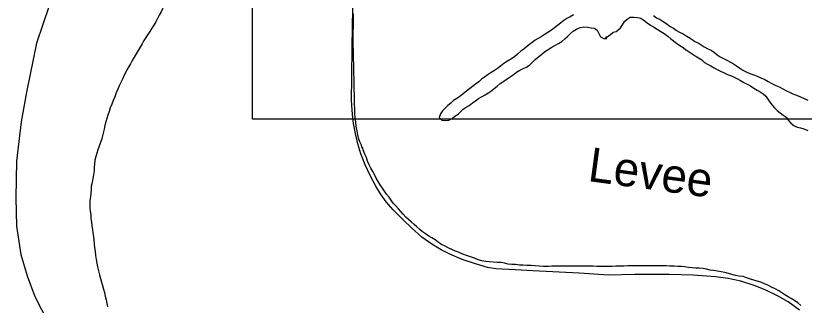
# Model space of a CAD drawing. Extents: x 1945482 to 2853149, y 66427 to 1015778.
# Drawn here: x 2297099 to 2300512, y 198481 to 199733 of the extents above; entities that cross this region are included whole.
import ezdxf

# ---------------------------------------------------------------- set-up
doc = ezdxf.new("R2010")
doc.units = 0
for name, color, linetype in [('Old_Level_21', 7, 'Continuous'), ('Old_Level_3', 7, 'Continuous'), ('Old_Level_35', 7, 'Continuous'), ('Old_Level_52', 7, 'Continuous'), ('Old_Level_60', 7, 'Continuous')]:
    doc.layers.add(name, color=color, linetype=linetype)

msp = doc.modelspace()

# ---------------------------------------------------------------- linework, layer by layer
at = {"layer": 'Old_Level_3'}
msp.add_lwpolyline([(2304961.1, 199286.1), (2298124.6, 199286.1), (2298124.6, 202204.8), (2304961.1, 202204.8), (2304961.1, 199286.1)], dxfattribs=at)
at = {"layer": 'Old_Level_35'}
msp.add_lwpolyline([(2300491.7, 198459.2), (2300442.2, 198495), (2300395.9, 198521.4), (2300342.9, 198547.7), (2300295.4, 198566.4), (2300237.4, 198584.2), (2300183.1, 198595.8), (2300127.2, 198603.1), (2300030.9, 198610.2), (2299927, 198613.5), (2299779.1, 198614.1), (2299665.2, 198611.1), (2299537.2, 198620.1), (2299337, 198630.3), (2299260.9, 198633.7), (2299177.1, 198638.9), (2299140.8, 198644.6), (2299088.9, 198660.3), (2299030.6, 198678.9), (2298978.6, 198701.2), (2298940.2, 198721), (2298900, 198744.4), (2298856.4, 198775.7), (2298811.5, 198815.6), (2298777.1, 198849.4), (2298733, 198892.9), (2298702.9, 198928.3), (2298678.3, 198962.5), (2298658, 198996.4), (2298633.6, 199042.1), (2298611.8, 199087.8), (2298592.8, 199135.7), (2298580.2, 199179.6), (2298569.9, 199223.4), (2298561.6, 199267.5), (2298557, 199305.3), (2298552.7, 199367.4), (2298553.9, 199465.4), (2298554.6, 199599.2), (2298557.5, 199765.5)], dxfattribs=at)
at = {"layer": 'Old_Level_52'}
msp.add_lwpolyline([(2297903, 202210.8), (2297795.6, 201641.6), (2297622.1, 200907.6), (2297545.5, 200618.8), (2297392.5, 200193.1), (2297315, 199980.3), (2297243.4, 199775.5), (2297189.3, 199614.8), (2297146.2, 199401.9), (2297123.3, 199274), (2297103.2, 199103.9), (2297099.5, 198945.2), (2297102.1, 198822.2), (2297121.9, 198700.2), (2297149.1, 198608.5), (2297182.1, 198518.9), (2297241.5, 198403.6)], dxfattribs=at)
at = {"layer": 'Old_Level_60'}
for points in [[(2297754.5, 199805.8), (2297747.7, 199791.4), (2297741.5, 199777.4), (2297735, 199763.4), (2297728.2, 199749.6), (2297720.7, 199735.4), (2297713.2, 199721.2)], [(2297713.2, 199721.2), (2297705.5, 199706.8), (2297697.2, 199692.8), (2297688.5, 199679.2), (2297679.5, 199665.2), (2297670.5, 199651.8), (2297662.2, 199638.6), (2297653.7, 199625.4), (2297646, 199611.6), (2297638, 199597.2), (2297629.5, 199582.6), (2297621, 199568.4), (2297612.2, 199553.8), (2297603.7, 199539.2), (2297595.5, 199525), (2297587.5, 199511.4), (2297580.5, 199498), (2297570.7, 199479.4), (2297560.7, 199458.6), (2297554.2, 199444.8), (2297547.5, 199430.4), (2297540.7, 199415.2), (2297534, 199399.4), (2297527.5, 199382.8), (2297521, 199366.2), (2297514.5, 199350.2), (2297508.7, 199334.2), (2297503.2, 199318.8), (2297498.2, 199303.6), (2297493.5, 199288.4), (2297489.2, 199273.6), (2297485.2, 199258), (2297481.5, 199241.8), (2297477.5, 199224.8), (2297473.5, 199208.2), (2297471.5, 199200), (2297454.7, 199153.4), (2297450.2, 199139.2), (2297445.5, 199123.6), (2297441.7, 199108.4), (2297440.5, 199093.2), (2297438.5, 199077), (2297438.2, 199061.6), (2297435.5, 199045.4), (2297432.5, 199029), (2297430, 199012.2), (2297426, 198996.2), (2297425.5, 198980.8), (2297425, 198965.2), (2297422.5, 198949.6), (2297420.5, 198934), (2297420.5, 198917.8), (2297420.5, 198902.6), (2297421.2, 198887.4), (2297424.5, 198871.4), (2297424.5, 198856.2), (2297427.7, 198840.8), (2297429.2, 198824.2), (2297431.2, 198808.4), (2297433.5, 198793.4), (2297435.7, 198778.2), (2297437.7, 198761.8), (2297438.5, 198745), (2297440.5, 198730), (2297442.5, 198714.6), (2297444.5, 198696), (2297447.2, 198679), (2297450.2, 198662.4), (2297453.7, 198646.8), (2297457.7, 198629), (2297462.5, 198612.2), (2297466.2, 198596.6), (2297470, 198581.2), (2297474.5, 198565.6), (2297479.5, 198550.4), (2297484, 198535.4), (2297487, 198520.6), (2297490.7, 198503.8), (2297493, 198488), (2297496.2, 198473.2)], [(2298598, 199160.4), (2298595.2, 199173), (2298589, 199187.4), (2298583.2, 199203.8), (2298579.5, 199218.4), (2298576.5, 199235.4), (2298573.2, 199254), (2298570.5, 199272.8), (2298568.2, 199291.6), (2298567.2, 199311.2), (2298566.5, 199331.6), (2298565.7, 199352.4), (2298565.2, 199372.6), (2298564.7, 199394), (2298564.5, 199410.2), (2298564, 199427.4), (2298563.5, 199443.2), (2298563.2, 199462.8), (2298562.7, 199483.6), (2298562.5, 199502), (2298562, 199524.2), (2298561.5, 199546.2), (2298561, 199564.2), (2298560.5, 199583.8), (2298560.2, 199602), (2298559.7, 199617.2), (2298559.5, 199641.6), (2298559.7, 199664.8), (2298560.5, 199686.2), (2298560.7, 199707.6), (2298560.7, 199724), (2298560.7, 199741.6)], [(2299512.5, 199737), (2299499, 199729), (2299484.5, 199721), (2299471.5, 199713), (2299457.2, 199701.2), (2299444.5, 199690.8), (2299431.5, 199680.4), (2299417.7, 199670.2), (2299402, 199660), (2299386.5, 199650.6), (2299373.7, 199642.6), (2299360.2, 199634.6), (2299347, 199626.8), (2299334, 199617.4), (2299322.2, 199608.2), (2299310, 199598.4), (2299297.5, 199589)], [(2299309.5, 199511.4), (2299323.7, 199520.4), (2299337.5, 199533.6), (2299347.7, 199544.4), (2299362.5, 199556.8), (2299376.2, 199567), (2299388, 199576.8), (2299403.5, 199587.6), (2299419.5, 199596.6), (2299432.7, 199604), (2299447.7, 199613.4), (2299462.2, 199622), (2299475, 199633.2), (2299487.2, 199644), (2299499.2, 199654.8), (2299511.2, 199666.8), (2299525.5, 199675.6), (2299541.5, 199682), (2299557.5, 199684.6), (2299574, 199684.4), (2299589.7, 199681.4), (2299604.5, 199678.8), (2299615, 199670.4), (2299623.2, 199656.2), (2299630.2, 199642.6), (2299644.2, 199635), (2299657.5, 199634.8), (2299653.7, 199642.4), (2299659.5, 199642.4), (2299673.5, 199651.4), (2299684.5, 199662), (2299697.2, 199664.4), (2299705.5, 199670.8), (2299716.5, 199681.2), (2299725, 199694.2), (2299733.7, 199707.6), (2299745, 199718), (2299758.2, 199727), (2299773.7, 199727), (2299789.5, 199725.8), (2299805.2, 199722.8), (2299818.5, 199713.2), (2299831.5, 199702.2), (2299846.5, 199692.6), (2299859.5, 199684.6), (2299875.5, 199674.4), (2299890.5, 199664.8), (2299905.2, 199655.8), (2299921.2, 199645.2), (2299934.5, 199633), (2299945.7, 199624.1), (2299947.1, 199623.1), (2299959.2, 199614.4), (2299973, 199605), (2299987, 199595.4), (2299999.2, 199586), (2300000, 199585.6), (2300014, 199577.4), (2300026.5, 199568), (2300039.7, 199559.6), (2300054.5, 199551), (2300068, 199543), (2300079.7, 199531.2), (2300093.5, 199523.2), (2300107.5, 199516.4), (2300121.5, 199508), (2300135.5, 199500.2), (2300149.5, 199492.8), (2300164.5, 199485.8), (2300179.2, 199479.4), (2300193.2, 199474.4), (2300207.7, 199467.6), (2300222.5, 199460.4), (2300236, 199453.4), (2300250.7, 199445), (2300264.7, 199437.8), (2300278.5, 199430), (2300293.5, 199420.2), (2300307.5, 199411.4), (2300321, 199403.8), (2300333.5, 199395.2), (2300345, 199384.6), (2300354, 199372.4), (2300362.2, 199359.2), (2300372.2, 199346.2), (2300382.5, 199334.4), (2300395, 199323.6), (2300407, 199312.6), (2300420.2, 199303), (2300433, 199293.8), (2300443.7, 199280.6), (2300454.2, 199268.4), (2300467, 199258.8), (2300481, 199250.6), (2300495.5, 199248.2), (2300510.5, 199244.2), (2300526.7, 199237.2)], [(2299859.5, 199733.6), (2299873, 199724.6), (2299888, 199717), (2299901.5, 199707.8), (2299916.5, 199697.6), (2299931.5, 199686.6), (2299945.5, 199680)], [(2299945.5, 199680), (2299958.7, 199670), (2299972.2, 199662.8), (2299988, 199654.8), (2300000, 199646.6), (2300003, 199644.6), (2300017.5, 199636.4), (2300030.5, 199627.8), (2300038.5, 199622.2), (2300052.7, 199616.6), (2300065.5, 199607.4), (2300079.2, 199598.6), (2300094.7, 199590), (2300109.5, 199583.8), (2300123, 199574.4), (2300134.5, 199564), (2300147.5, 199555.6), (2300162.2, 199548.4), (2300179.7, 199540.2), (2300193, 199532.6), (2300205.7, 199524.6), (2300219.2, 199516.4), (2300232.5, 199507), (2300246.5, 199497.6), (2300260.5, 199490), (2300276.7, 199482.6), (2300293.5, 199477.2), (2300308, 199471.6), (2300323.7, 199464.8), (2300340.5, 199456.8), (2300355.5, 199449), (2300371, 199440.4), (2300388.5, 199431.8), (2300402.5, 199425.4), (2300418.5, 199416.6), (2300434.5, 199408.2), (2300448, 199402.2), (2300462.5, 199395.8), (2300478.7, 199389.2), (2300495.5, 199382.4), (2300511.5, 199375.6), (2300527.2, 199368.6)], [(2299297.5, 199589), (2299285.7, 199579.6), (2299271.2, 199567), (2299259.2, 199557), (2299244.5, 199546.8), (2299228.2, 199537.2), (2299212, 199526.8), (2299197, 199515.6), (2299183.7, 199505.6), (2299170.7, 199496.6), (2299157.5, 199487.8), (2299143.5, 199478.4), (2299127.5, 199467.8), (2299115.2, 199458.2), (2299103.5, 199447.6), (2299089.5, 199436.6), (2299076, 199426.6), (2299063, 199416.8), (2299050, 199406.8), (2299035, 199394.6), (2299021.5, 199384.2), (2299008.5, 199375.6), (2298994.5, 199365.8), (2298982, 199354.4), (2298969.7, 199344.2), (2298957.5, 199332.8), (2298946.5, 199322), (2298937.2, 199308.2), (2298932, 199293), (2298943.2, 199281.8), (2298957.5, 199279.8), (2298973.2, 199281.4), (2298987.7, 199289), (2299000.2, 199298.2), (2299013.5, 199307.4), (2299025, 199318.6), (2299035.7, 199329), (2299048.7, 199337), (2299062.2, 199345.4), (2299075.5, 199356.2), (2299089.5, 199365.6), (2299102, 199374.6), (2299117.5, 199383.4), (2299131.5, 199391), (2299146, 199400.4), (2299159, 199409.2), (2299170.5, 199418.6), (2299182.5, 199428.8), (2299196, 199439.4), (2299211.5, 199450.2), (2299225.7, 199460.6), (2299238.5, 199469), (2299252.5, 199477.8), (2299266.5, 199488.8), (2299280.5, 199497.4), (2299295.5, 199504.4), (2299309.5, 199511.4)], [(2299279.5, 198654.6), (2299261.5, 198656.6), (2299246, 198657.6), (2299230.2, 198658.4), (2299215, 198662.2), (2299199.5, 198665.8), (2299183.2, 198665.6), (2299165.5, 198666.4), (2299149.5, 198668.4), (2299133.5, 198670), (2299116.5, 198673.2), (2299101.2, 198677.4), (2299084.2, 198684.2), (2299067.7, 198690.8), (2299050.5, 198696.4), (2299034.7, 198701.6), (2299018.5, 198708.2), (2299002.2, 198715), (2298986.5, 198721.6), (2298971, 198728.8), (2298957.2, 198736.8), (2298941.5, 198743.8), (2298928.2, 198752), (2298914, 198763), (2298899.5, 198772), (2298887, 198780.2), (2298872.5, 198790.2), (2298859.7, 198798.6), (2298847.5, 198807.8), (2298835.5, 198819.4), (2298823, 198830.6), (2298810.5, 198841.2), (2298799, 198851.4), (2298787.5, 198861.6), (2298776.5, 198875), (2298766.5, 198886.6), (2298755.7, 198897.6), (2298744, 198910.2), (2298733, 198923), (2298724.2, 198935.4), (2298715, 198947.8), (2298704.5, 198961.2), (2298695, 198974.2), (2298686.5, 198987), (2298676.5, 199001.8), (2298667.5, 199016.2), (2298659.2, 199030.8), (2298651.7, 199045.8), (2298644.5, 199059), (2298636.5, 199073.8), (2298628.7, 199088.8), (2298622.2, 199104.2), (2298617.5, 199119.4), (2298610.5, 199134.4), (2298605, 199149.4), (2298599.5, 199163.6), (2298598, 199160.4)], [(2300496.5, 198480.2), (2300484.2, 198491), (2300469.7, 198500.6), (2300455.2, 198509.8), (2300442, 198517.4), (2300428.2, 198526), (2300415, 198534.4), (2300402, 198542.6), (2300385.5, 198551.8), (2300369.7, 198559.4), (2300353.5, 198567), (2300339.7, 198573.8), (2300323.5, 198580.2), (2300308.5, 198584.2), (2300293.5, 198588.6), (2300279, 198593.6), (2300262.2, 198599.8), (2300247.2, 198604.4), (2300230.7, 198607.2), (2300214.7, 198610), (2300198.5, 198614.2), (2300184, 198618.2), (2300168, 198622.4), (2300152, 198624.8), (2300135.7, 198627.6), (2300121, 198630.4), (2300104.7, 198633), (2300089, 198636.4), (2300074, 198639.4), (2300057.2, 198641), (2300042, 198641.4), (2300027, 198642.6), (2300011.5, 198644.4), (2300000, 198646), (2299995.5, 198646.6), (2299980, 198648), (2299964.7, 198649), (2299948.7, 198649.8), (2299930, 198650.2), (2299914.2, 198650.6), (2299893, 198650.8), (2299876, 198651), (2299858.5, 198651.2), (2299836.5, 198651.4), (2299821.2, 198651.8), (2299800.7, 198651.6), (2299783.2, 198651.4), (2299765.5, 198651), (2299748.5, 198650.6), (2299731.2, 198650.2), (2299711, 198649.8), (2299695.7, 198649.4), (2299680.5, 198649), (2299664.5, 198648.8), (2299647.7, 198648.4), (2299630.2, 198648.4), (2299614.5, 198648.8), (2299597.5, 198649.2), (2299580.2, 198649.8), (2299563.5, 198650), (2299548, 198649.8), (2299528, 198649.8), (2299509.5, 198649.6), (2299492, 198649.6), (2299474, 198649.6), (2299457, 198649.8), (2299439, 198649.6), (2299419.5, 198649.2), (2299404.2, 198649), (2299383.2, 198648.8), (2299365.2, 198649.4), (2299347.5, 198650.8), (2299330.5, 198652.2), (2299311.5, 198653), (2299295, 198653.4), (2299279.5, 198654.6)]]:
    msp.add_lwpolyline(points, dxfattribs=at)

# ---------------------------------------------------------------- texts
at = {"layer": 'Old_Level_21'}
msp.add_text('Levee', height=147.64, rotation=352.2638, dxfattribs=at).set_placement((2299571.3, 199018.6))

doc.saveas('drawing.dxf')
